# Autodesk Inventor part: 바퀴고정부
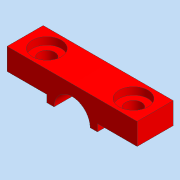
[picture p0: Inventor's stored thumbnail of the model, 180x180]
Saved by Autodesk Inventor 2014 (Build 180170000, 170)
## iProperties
Company: 한국ATC센터
Created: 2015-05
Part Number: 바퀴고정부
Document SubType Name: 모델링
Designer: KYOUNG IL JANG
Vendor: CBT Solutions
Material: 일반
Appearance: 기본값
Author: KYOUNG IL JANG
Comments: 파생
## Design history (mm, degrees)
derived "바퀴고정부.ipt"
node "솔리드1"
node "솔리드 본체"
node "곡면 본체"
feature "솔리드1::바퀴고정부.ipt" dims "d0" = 10
tag "피쳐 태그1"
